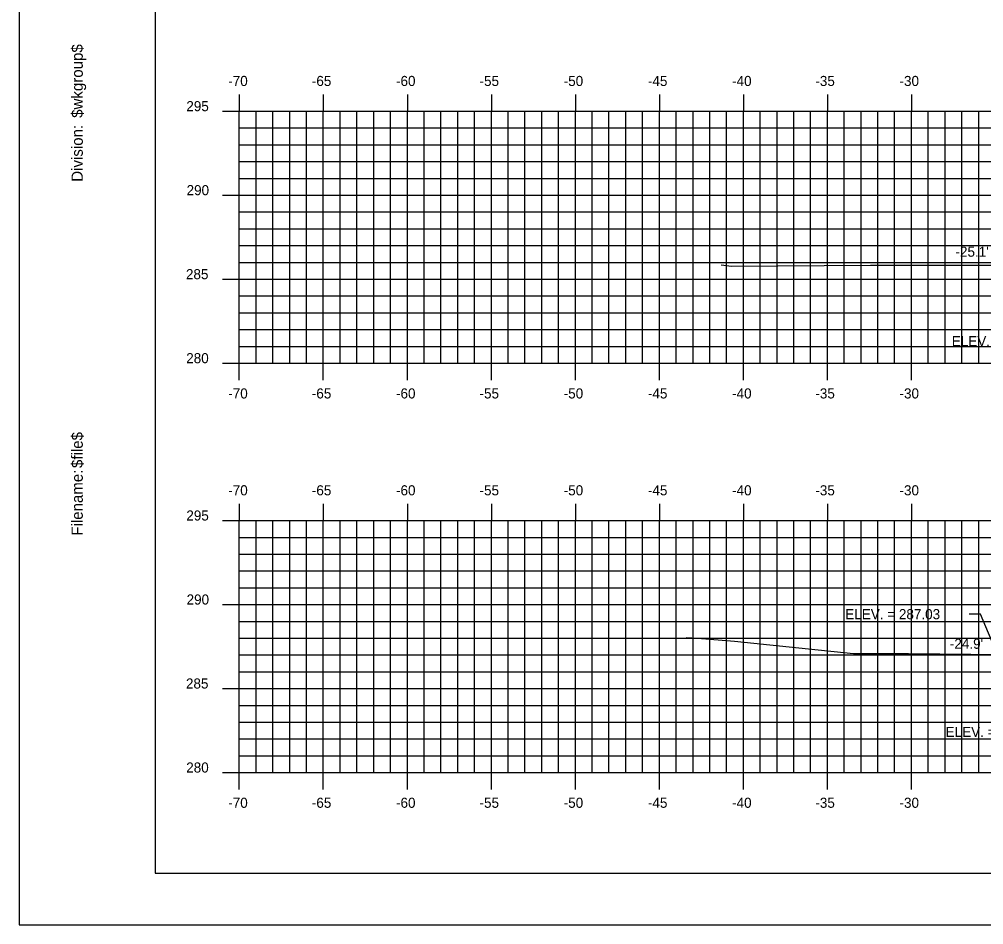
# Model space of a CAD drawing. Extents: x 852672 to 852842, y 366268 to 366378.
# Drawn here: x 852672 to 852729.4, y 366268.2 to 366322.1 of the extents above; entities that cross this region are included whole.
import ezdxf

# ---------------------------------------------------------------- set-up
doc = ezdxf.new("R2010")
doc.units = 0
for name, color, linetype in [('BORDER', 7, 'Continuous'), ('D_Text_Standard', 7, 'Continuous'), ('H_V ANNOTATION', 7, 'Continuous'), ('MAJOR', 7, 'Continuous'), ('MINOR', 7, 'Continuous'), ('PLOT BOUNDARY', 7, 'Continuous'), ('S_Roadway_Centerline', 7, 'Continuous')]:
    doc.layers.add(name, color=color, linetype=linetype)

msp = doc.modelspace()

# ---------------------------------------------------------------- linework, layer by layer
at = {"layer": 'BORDER'}
for p, q in [((852680.097, 366376.236), (852680.097, 366271.236)), ((852680.097, 366271.236), (852840.097, 366271.236))]:
    msp.add_line(p, q, dxfattribs=at)
at = {"layer": 'D_Text_Standard'}
msp.add_lwpolyline([(852730.214, 366284.265), (852729.202, 366286.663), (852728.522, 366286.663)], dxfattribs=at)
at = {"layer": 'MAJOR'}
for p, q in [((852685.096, 366317.604), (852685.096, 366316.602)), ((852690.096, 366317.604), (852690.096, 366316.602)), ((852695.096, 366317.604), (852695.096, 366316.602)), ((852700.096, 366317.604), (852700.096, 366316.602)), ((852705.096, 366317.604), (852705.096, 366316.602)), ((852710.096, 366317.604), (852710.096, 366316.602)), ((852715.096, 366317.604), (852715.096, 366316.602)), ((852720.096, 366317.604), (852720.096, 366316.602)), ((852725.096, 366317.604), (852725.096, 366316.602)), ((852684.094, 366316.602), (852685.096, 366316.602)), ((852685.096, 366316.602), (852825.096, 366316.602)), ((852685.096, 366301.602), (852685.096, 366316.602)), ((852685.096, 366301.602), (852685.096, 366316.602)), ((852685.096, 366316.602), (852825.096, 366316.602)), ((852690.096, 366301.602), (852690.096, 366316.602)), ((852695.096, 366301.602), (852695.096, 366316.602)), ((852700.096, 366301.602), (852700.096, 366316.602)), ((852705.096, 366301.602), (852705.096, 366316.602)), ((852710.096, 366301.602), (852710.096, 366316.602)), ((852715.096, 366301.602), (852715.096, 366316.602)), ((852720.096, 366301.602), (852720.096, 366316.602)), ((852725.096, 366301.602), (852725.096, 366316.602)), ((852684.094, 366311.602), (852685.096, 366311.602)), ((852685.096, 366311.602), (852825.096, 366311.602)), ((852684.094, 366306.602), (852685.096, 366306.602)), ((852685.096, 366306.602), (852825.096, 366306.602)), ((852684.094, 366301.602), (852685.096, 366301.602)), ((852685.096, 366301.602), (852825.096, 366301.602)), ((852685.096, 366301.602), (852825.096, 366301.602)), ((852685.096, 366300.6), (852685.096, 366301.602)), ((852690.096, 366300.6), (852690.096, 366301.602)), ((852695.096, 366300.6), (852695.096, 366301.602)), ((852700.096, 366300.6), (852700.096, 366301.602)), ((852705.096, 366300.6), (852705.096, 366301.602)), ((852710.096, 366300.6), (852710.096, 366301.602)), ((852715.096, 366300.6), (852715.096, 366301.602)), ((852720.096, 366300.6), (852720.096, 366301.602)), ((852725.096, 366300.6), (852725.096, 366301.602)), ((852685.096, 366293.238), (852685.096, 366292.236)), ((852690.096, 366293.238), (852690.096, 366292.236)), ((852695.096, 366293.238), (852695.096, 366292.236)), ((852700.096, 366293.238), (852700.096, 366292.236)), ((852705.096, 366293.238), (852705.096, 366292.236)), ((852710.096, 366293.238), (852710.096, 366292.236)), ((852715.096, 366293.238), (852715.096, 366292.236)), ((852720.096, 366293.238), (852720.096, 366292.236)), ((852725.096, 366293.238), (852725.096, 366292.236)), ((852684.094, 366292.236), (852685.096, 366292.236)), ((852685.096, 366292.236), (852825.096, 366292.236)), ((852685.096, 366277.236), (852685.096, 366292.236)), ((852685.096, 366277.236), (852685.096, 366292.236)), ((852685.096, 366292.236), (852825.096, 366292.236)), ((852690.096, 366277.236), (852690.096, 366292.236)), ((852695.096, 366277.236), (852695.096, 366292.236)), ((852700.096, 366277.236), (852700.096, 366292.236)), ((852705.096, 366277.236), (852705.096, 366292.236)), ((852710.096, 366277.236), (852710.096, 366292.236)), ((852715.096, 366277.236), (852715.096, 366292.236)), ((852720.096, 366277.236), (852720.096, 366292.236)), ((852725.096, 366277.236), (852725.096, 366292.236)), ((852684.094, 366287.236), (852685.096, 366287.236)), ((852685.096, 366287.236), (852825.096, 366287.236)), ((852684.094, 366282.236), (852685.096, 366282.236)), ((852685.096, 366282.236), (852825.096, 366282.236)), ((852684.094, 366277.236), (852685.096, 366277.236)), ((852685.096, 366277.236), (852825.096, 366277.236)), ((852685.096, 366276.234), (852685.096, 366277.236)), ((852690.096, 366276.234), (852690.096, 366277.236)), ((852695.096, 366276.234), (852695.096, 366277.236)), ((852700.096, 366276.234), (852700.096, 366277.236)), ((852705.096, 366276.234), (852705.096, 366277.236)), ((852710.096, 366276.234), (852710.096, 366277.236)), ((852715.096, 366276.234), (852715.096, 366277.236)), ((852720.096, 366276.234), (852720.096, 366277.236)), ((852725.096, 366276.234), (852725.096, 366277.236))]:
    msp.add_line(p, q, dxfattribs=at)
at = {"layer": 'MINOR'}
for p, q in [((852686.096, 366301.602), (852686.096, 366316.602)), ((852687.096, 366301.602), (852687.096, 366316.602)), ((852688.096, 366301.602), (852688.096, 366316.602)), ((852689.096, 366301.602), (852689.096, 366316.602)), ((852691.096, 366301.602), (852691.096, 366316.602)), ((852692.096, 366301.602), (852692.096, 366316.602)), ((852693.096, 366301.602), (852693.096, 366316.602)), ((852694.096, 366301.602), (852694.096, 366316.602)), ((852696.096, 366301.602), (852696.096, 366316.602)), ((852697.096, 366301.602), (852697.096, 366316.602)), ((852698.096, 366301.602), (852698.096, 366316.602)), ((852699.096, 366301.602), (852699.096, 366316.602)), ((852701.096, 366301.602), (852701.096, 366316.602)), ((852702.096, 366301.602), (852702.096, 366316.602)), ((852703.096, 366301.602), (852703.096, 366316.602)), ((852704.096, 366301.602), (852704.096, 366316.602)), ((852706.096, 366301.602), (852706.096, 366316.602)), ((852707.096, 366301.602), (852707.096, 366316.602)), ((852708.096, 366301.602), (852708.096, 366316.602)), ((852709.096, 366301.602), (852709.096, 366316.602)), ((852711.096, 366301.602), (852711.096, 366316.602)), ((852712.096, 366301.602), (852712.096, 366316.602)), ((852713.096, 366301.602), (852713.096, 366316.602)), ((852714.096, 366301.602), (852714.096, 366316.602)), ((852716.096, 366301.602), (852716.096, 366316.602)), ((852717.096, 366301.602), (852717.096, 366316.602)), ((852718.096, 366301.602), (852718.096, 366316.602)), ((852719.096, 366301.602), (852719.096, 366316.602)), ((852721.096, 366301.602), (852721.096, 366316.602)), ((852722.096, 366301.602), (852722.096, 366316.602)), ((852723.096, 366301.602), (852723.096, 366316.602)), ((852724.096, 366301.602), (852724.096, 366316.602)), ((852726.096, 366301.602), (852726.096, 366316.602)), ((852727.096, 366301.602), (852727.096, 366316.602)), ((852728.096, 366301.602), (852728.096, 366316.602)), ((852729.096, 366301.602), (852729.096, 366316.602)), ((852685.096, 366315.602), (852825.096, 366315.602)), ((852685.096, 366315.602), (852686.098, 366315.602)), ((852685.096, 366314.602), (852825.096, 366314.602)), ((852685.096, 366314.602), (852686.098, 366314.602)), ((852685.096, 366313.602), (852825.096, 366313.602)), ((852685.096, 366313.602), (852686.098, 366313.602)), ((852685.096, 366312.602), (852825.096, 366312.602)), ((852685.096, 366312.602), (852686.098, 366312.602)), ((852685.096, 366310.602), (852825.096, 366310.602)), ((852685.096, 366310.602), (852686.098, 366310.602)), ((852685.096, 366309.602), (852825.096, 366309.602)), ((852685.096, 366309.602), (852686.098, 366309.602)), ((852685.096, 366308.602), (852825.096, 366308.602)), ((852685.096, 366308.602), (852686.098, 366308.602)), ((852685.096, 366307.602), (852825.096, 366307.602)), ((852685.096, 366307.602), (852686.098, 366307.602)), ((852685.096, 366305.602), (852825.096, 366305.602)), ((852685.096, 366305.602), (852686.098, 366305.602)), ((852685.096, 366304.602), (852825.096, 366304.602)), ((852685.096, 366304.602), (852686.098, 366304.602)), ((852685.096, 366303.602), (852825.096, 366303.602)), ((852685.096, 366303.602), (852686.098, 366303.602)), ((852685.096, 366302.602), (852825.096, 366302.602)), ((852685.096, 366302.602), (852686.098, 366302.602)), ((852686.096, 366277.236), (852686.096, 366292.236)), ((852687.096, 366277.236), (852687.096, 366292.236)), ((852688.096, 366277.236), (852688.096, 366292.236)), ((852689.096, 366277.236), (852689.096, 366292.236)), ((852691.096, 366277.236), (852691.096, 366292.236)), ((852692.096, 366277.236), (852692.096, 366292.236)), ((852693.096, 366277.236), (852693.096, 366292.236)), ((852694.096, 366277.236), (852694.096, 366292.236)), ((852696.096, 366277.236), (852696.096, 366292.236)), ((852697.096, 366277.236), (852697.096, 366292.236)), ((852698.096, 366277.236), (852698.096, 366292.236)), ((852699.096, 366277.236), (852699.096, 366292.236)), ((852701.096, 366277.236), (852701.096, 366292.236)), ((852702.096, 366277.236), (852702.096, 366292.236)), ((852703.096, 366277.236), (852703.096, 366292.236)), ((852704.096, 366277.236), (852704.096, 366292.236)), ((852706.096, 366277.236), (852706.096, 366292.236)), ((852707.096, 366277.236), (852707.096, 366292.236)), ((852708.096, 366277.236), (852708.096, 366292.236)), ((852709.096, 366277.236), (852709.096, 366292.236)), ((852711.096, 366277.236), (852711.096, 366292.236)), ((852712.096, 366277.236), (852712.096, 366292.236)), ((852713.096, 366277.236), (852713.096, 366292.236)), ((852714.096, 366277.236), (852714.096, 366292.236)), ((852716.096, 366277.236), (852716.096, 366292.236)), ((852717.096, 366277.236), (852717.096, 366292.236)), ((852718.096, 366277.236), (852718.096, 366292.236)), ((852719.096, 366277.236), (852719.096, 366292.236)), ((852721.096, 366277.236), (852721.096, 366292.236)), ((852722.096, 366277.236), (852722.096, 366292.236)), ((852723.096, 366277.236), (852723.096, 366292.236)), ((852724.096, 366277.236), (852724.096, 366292.236)), ((852726.096, 366277.236), (852726.096, 366292.236)), ((852727.096, 366277.236), (852727.096, 366292.236)), ((852728.096, 366277.236), (852728.096, 366292.236)), ((852729.096, 366277.236), (852729.096, 366292.236)), ((852685.096, 366291.236), (852825.096, 366291.236)), ((852685.096, 366291.236), (852686.098, 366291.236)), ((852685.096, 366290.236), (852825.096, 366290.236)), ((852685.096, 366290.236), (852686.098, 366290.236)), ((852685.096, 366289.236), (852825.096, 366289.236)), ((852685.096, 366289.236), (852686.098, 366289.236)), ((852685.096, 366288.236), (852825.096, 366288.236)), ((852685.096, 366288.236), (852686.098, 366288.236)), ((852685.096, 366286.236), (852825.096, 366286.236)), ((852685.096, 366286.236), (852686.098, 366286.236)), ((852685.096, 366285.236), (852825.096, 366285.236)), ((852685.096, 366285.236), (852686.098, 366285.236)), ((852685.096, 366284.236), (852825.096, 366284.236)), ((852685.096, 366284.236), (852686.098, 366284.236)), ((852685.096, 366283.236), (852825.096, 366283.236)), ((852685.096, 366283.236), (852686.098, 366283.236)), ((852685.096, 366281.236), (852825.096, 366281.236)), ((852685.096, 366281.236), (852686.098, 366281.236)), ((852685.096, 366280.236), (852825.096, 366280.236)), ((852685.096, 366280.236), (852686.098, 366280.236)), ((852685.096, 366279.236), (852825.096, 366279.236)), ((852685.096, 366279.236), (852686.098, 366279.236)), ((852685.096, 366278.236), (852825.096, 366278.236)), ((852685.096, 366278.236), (852686.098, 366278.236))]:
    msp.add_line(p, q, dxfattribs=at)
at = {"layer": 'PLOT BOUNDARY'}
msp.add_lwpolyline([(852672.003, 366268.177), (852842.003, 366268.177), (852842.003, 366378.177), (852672.003, 366378.177)], close=True, dxfattribs=at)
at = {"layer": 'S_Roadway_Centerline'}
for points in [[(852713.77, 366307.449), (852714.386, 366307.384), (852722.656, 366307.437), (852728.866, 366307.44), (852729.91, 366307.44)], [(852711.688, 366285.283), (852712.372, 366285.239), (852714.568, 366285.064), (852721.649, 366284.317), (852723.226, 366284.327), (852724.924, 366284.328), (852730.5, 366284.261)]]:
    msp.add_lwpolyline(points, dxfattribs=at)

# ---------------------------------------------------------------- texts
at = {"layer": 'BORDER'}
for s, p in [('$wkgroup$', (852675.782, 366316.206)), ('Division:', (852675.782, 366312.403)), ('$file$', (852675.782, 366295.362)), ('Filename:', (852675.782, 366291.335))]:
    msp.add_text(s, height=0.6696, rotation=90, dxfattribs=at).set_placement(p)
at = {"layer": 'D_Text_Standard'}
for s, p in [("-25.1'", (852727.716, 366307.939)), ('ELEV. = 281.31', (852727.496, 366302.612)), ('ELEV. = 287.03', (852721.159, 366286.363)), ("-24.9'", (852727.383, 366284.603)), ('ELEV. = 282.42', (852727.131, 366279.356))]:
    msp.add_text(s, height=0.6, dxfattribs=at).set_placement(p)
at = {"layer": 'H_V ANNOTATION'}
for s, p in [('-70', (852684.438, 366318.102)), ('-65', (852689.414, 366318.102)), ('-60', (852694.422, 366318.102)), ('-55', (852699.393, 366318.102)), ('-50', (852704.401, 366318.102)), ('-45', (852709.414, 366318.102)), ('-40', (852714.422, 366318.102)), ('-35', (852719.377, 366318.102)), ('-30', (852724.385, 366318.102)), ('295', (852681.943, 366316.602)), ('290', (852681.959, 366311.602)), ('285', (852681.921, 366306.602)), ('280', (852681.937, 366301.602)), ('-70', (852684.438, 366299.502)), ('-65', (852689.414, 366299.502)), ('-60', (852694.422, 366299.502)), ('-55', (852699.393, 366299.502)), ('-50', (852704.401, 366299.502)), ('-45', (852709.414, 366299.502)), ('-40', (852714.422, 366299.502)), ('-35', (852719.377, 366299.502)), ('-30', (852724.385, 366299.502)), ('-70', (852684.438, 366293.736)), ('-65', (852689.414, 366293.736)), ('-60', (852694.422, 366293.736)), ('-55', (852699.393, 366293.736)), ('-50', (852704.401, 366293.736)), ('-45', (852709.414, 366293.736)), ('-40', (852714.422, 366293.736)), ('-35', (852719.377, 366293.736)), ('-30', (852724.385, 366293.736)), ('295', (852681.943, 366292.236)), ('290', (852681.959, 366287.236)), ('285', (852681.921, 366282.236)), ('280', (852681.937, 366277.236)), ('-70', (852684.438, 366275.136)), ('-65', (852689.414, 366275.136)), ('-60', (852694.422, 366275.136)), ('-55', (852699.393, 366275.136)), ('-50', (852704.401, 366275.136)), ('-45', (852709.414, 366275.136)), ('-40', (852714.422, 366275.136)), ('-35', (852719.377, 366275.136)), ('-30', (852724.385, 366275.136))]:
    msp.add_text(s, height=0.6, dxfattribs=at).set_placement(p)

doc.saveas('drawing.dxf')
